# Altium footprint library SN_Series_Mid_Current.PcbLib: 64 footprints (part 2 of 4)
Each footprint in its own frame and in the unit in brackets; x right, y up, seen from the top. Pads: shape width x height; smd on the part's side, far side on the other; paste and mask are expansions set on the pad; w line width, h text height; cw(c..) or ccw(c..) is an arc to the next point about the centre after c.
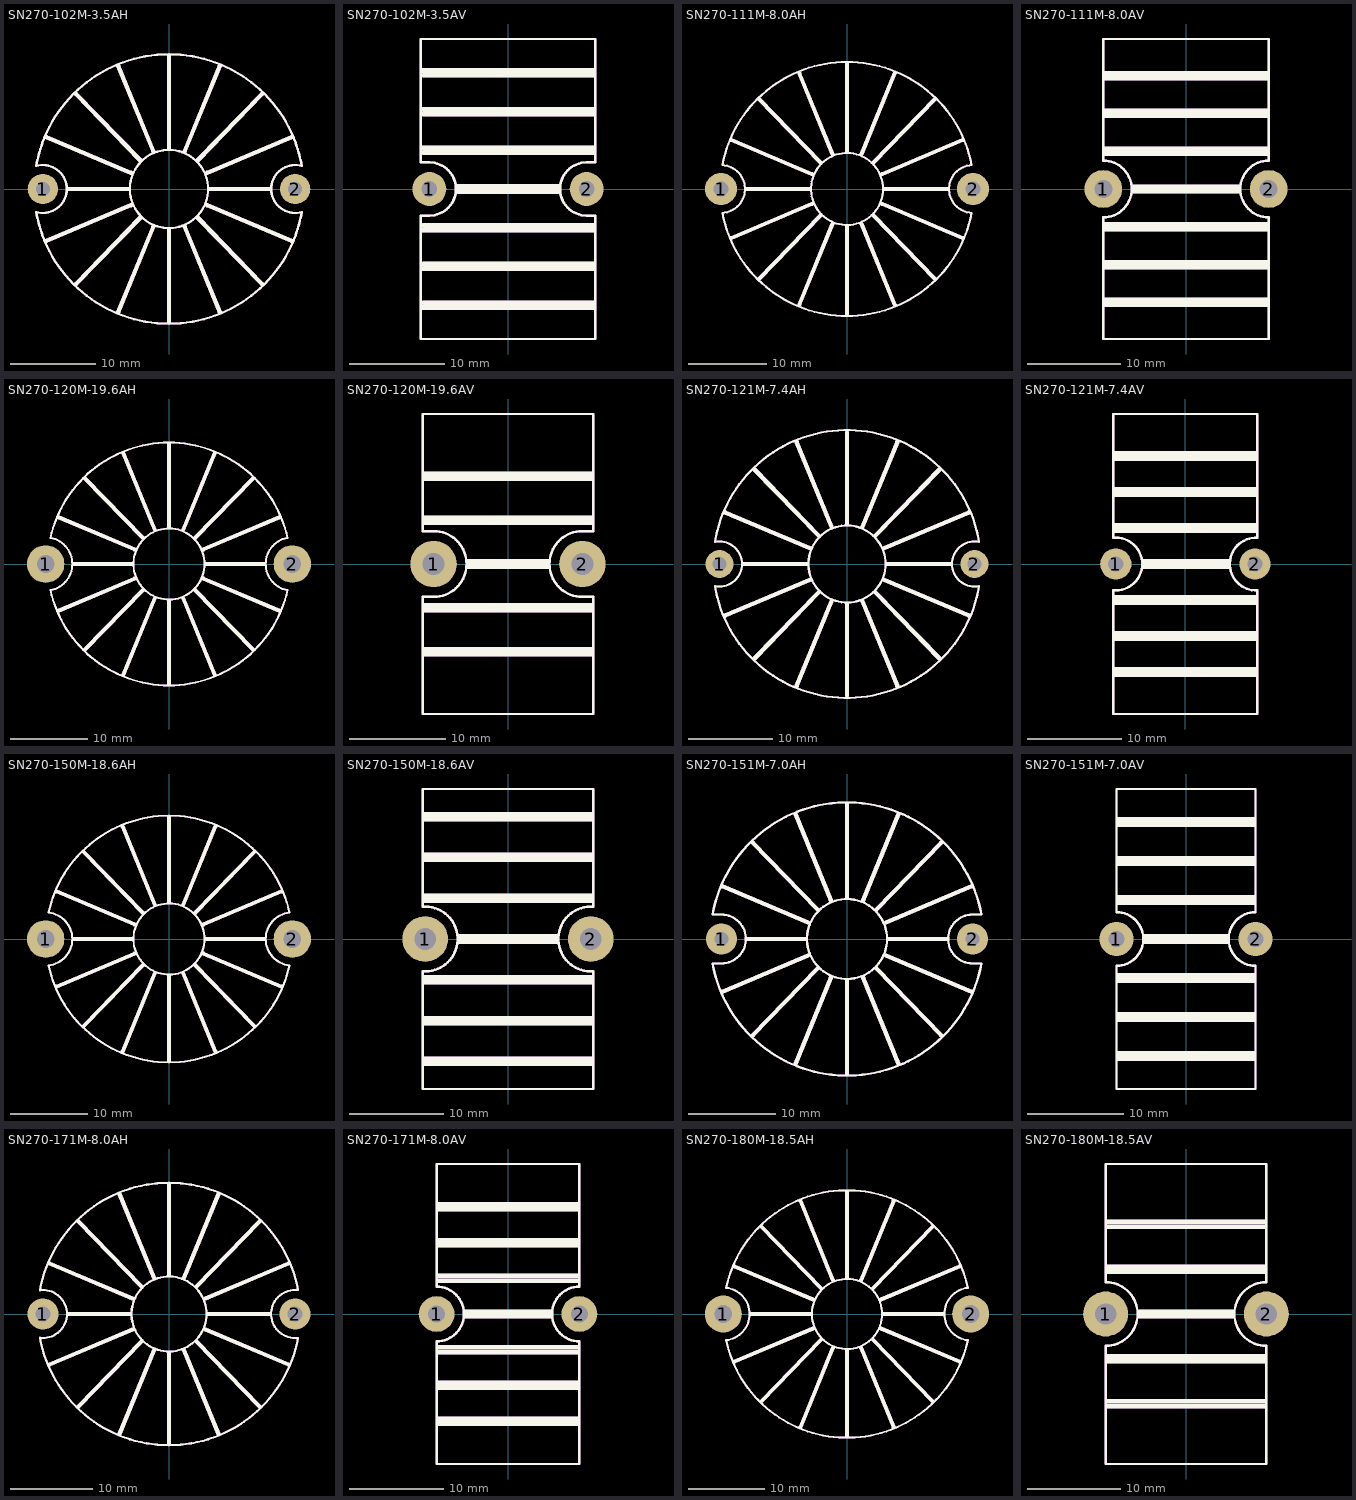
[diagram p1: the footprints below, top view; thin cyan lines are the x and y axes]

## SN270-102M-3.5AH [mil]
pads (2):
  round 140 hole 65: 1(-580,0) 2(580,0)
Top Overlay:
  circle w10: c0,0 r180
  lines w10: -610.95,-105.56 ccw(c0,0) 610.95,-105.56 cw(c580,0) 610.95,105.56 ccw(c0,0) -610.95,105.56 cw(c-580,0) -610.95,-105.56
  lines w19.68: -566.62,-240.1 -175.3,-74.28 ; -566.62,240.1 -175.3,74.28 ; -465,0 -185,0 ; -428.33,-437.64 -132.5,-132.5 ; -428.33,437.64 -132.5,132.5 ; -233.63,-567.25 -72.46,-173.99 ; -233.63,567.25 -72.46,173.99 ; 0,-610 0,-185 ; 0,185 0,610 ; 72.46,-173.99 233.63,-567.25 ; 72.46,173.99 233.63,567.25 ; 132.5,-132.5 428.33,-437.64 ; 132.5,132.5 428.33,437.64 ; 175.3,-74.28 566.62,-240.1 ; 175.3,74.28 566.62,240.1 ; 185,0 465,0
Mechanical 29:
  circle w10: c0,0 r180
  lines w10: -610.95,-105.56 ccw(c0,0) 610.95,-105.56 cw(c580,0) 610.95,105.56 ccw(c0,0) -610.95,105.56 cw(c-580,0) -610.95,-105.56
  lines w19.68: -566.62,-240.1 -175.3,-74.28 ; -566.62,240.1 -175.3,74.28 ; -465,0 -185,0 ; -428.33,-437.64 -132.5,-132.5 ; -428.33,437.64 -132.5,132.5 ; -233.63,-567.25 -72.46,-173.99 ; -233.63,567.25 -72.46,173.99 ; 0,-610 0,-185 ; 0,185 0,610 ; 72.46,-173.99 233.63,-567.25 ; 72.46,173.99 233.63,567.25 ; 132.5,-132.5 428.33,-437.64 ; 132.5,132.5 428.33,437.64 ; 175.3,-74.28 566.62,-240.1 ; 175.3,74.28 566.62,240.1 ; 185,0 465,0
  text "'.Designator'" at -290,145.15 h400

## SN270-102M-3.5AV [mil]
pads (2):
  round 140 hole 65: 1(-325,0) 2(325,0)
Top Overlay:
  lines w10: -360,-620 360,-620 360,-110 325,-110 cw(c325,0) 325,110 360,110 360,620 -360,620 -360,110 -325,110 cw(c-325,0) -325,-110 -360,-110 -360,-620
  lines w19.68: -355,-490 355,-490 ; -355,-330 355,-330 ; -355,-170 355,-170 ; -355,170 355,170 ; -355,330 355,330 ; -355,490 355,490 ; -350,-470 355,-470 ; -350,-310 355,-310 ; -350,-150 355,-150 ; -350,150 355,150 ; -350,310 355,310 ; -350,470 355,470 ; -210,-10 208,-10 ; -210,10 208,10
Mechanical 29:
  lines w10: -360,-620 360,-620 360,-110 325,-110 cw(c325,0) 325,110 360,110 360,620 -360,620 -360,110 -325,110 cw(c-325,0) -325,-110 -360,-110 -360,-620
  lines w19.68: -355,-490 355,-490 ; -355,-330 355,-330 ; -355,-170 355,-170 ; -355,170 355,170 ; -355,330 355,330 ; -355,490 355,490 ; -350,-470 355,-470 ; -350,-310 355,-310 ; -350,-150 355,-150 ; -350,150 355,150 ; -350,310 355,310 ; -350,470 355,470 ; -210,-10 208,-10 ; -210,10 208,10
  text "'.Designator'" at -1750,-64.85 h400

## SN270-111M-8.0AH [mil]
pads (2):
  round 160 hole 76: 1(-630,0) 2(630,0)
Top Overlay:
  circle w10: c0,0 r180
  lines w10: -623.53,-120.17 ccw(c0,0) 623.53,-120.17 ; -623.54,-119.83 ccw(c-630,0) -623.54,119.83 ; -623.53,120.17 cw(c0,0) 623.53,120.17 ; 623.54,-119.83 cw(c630,0) 623.54,119.83
  lines w19.68: -579.73,-245.65 -175.3,-74.28 ; -579.73,245.65 -175.3,74.28 ; -505,0 -185,0 ; -440.16,-449.85 -132.5,-132.5 ; -440.16,449.85 -132.5,132.5 ; -238.3,-578.65 -72.46,-173.99 ; -238.3,578.65 -72.46,173.99 ; 0,-630 0,-185 ; 0,185 0,630 ; 72.46,-173.99 239.02,-580.4 ; 72.46,173.99 239.02,580.4 ; 132.5,-132.5 440.16,-449.85 ; 132.5,132.5 440.16,449.85 ; 175.3,-74.28 579.73,-245.65 ; 175.3,74.28 579.73,245.65 ; 185,0 505,0
Mechanical 29:
  circle w10: c0,0 r180
  lines w10: -623.53,-120.17 ccw(c0,0) 623.53,-120.17 ; -623.54,-119.83 ccw(c-630,0) -623.54,119.83 ; -623.53,120.17 cw(c0,0) 623.53,120.17 ; 623.54,-119.83 cw(c630,0) 623.54,119.83
  lines w19.68: -579.73,-245.65 -175.3,-74.28 ; -579.73,245.65 -175.3,74.28 ; -505,0 -185,0 ; -440.16,-449.85 -132.5,-132.5 ; -440.16,449.85 -132.5,132.5 ; -238.3,-578.65 -72.46,-173.99 ; -238.3,578.65 -72.46,173.99 ; 0,-630 0,-185 ; 0,185 0,630 ; 72.46,-173.99 239.02,-580.4 ; 72.46,173.99 239.02,580.4 ; 132.5,-132.5 440.16,-449.85 ; 132.5,132.5 440.16,449.85 ; 175.3,-74.28 579.73,-245.65 ; 175.3,74.28 579.73,245.65 ; 185,0 505,0
  text "'.Designator'" at -290,145.15 h400

## SN270-111M-8.0AV [mil]
pads (2):
  round 160 hole 76: 1(-350,0) 2(350,0)
Top Overlay:
  lines w10: -350,-635 350,-635 350,-120 cw(c350,0) 350,120 350,635 -350,635 -350,120 cw(c-350,0) -350,-120 -350,-635
  lines w19.68: -345,-490 345,-490 ; -345,-470 345,-470 ; -345,-330 345,-330 ; -345,-310 345,-310 ; -345,-170 345,-170 ; -345,-150 345,-150 ; -345,150 345,150 ; -345,170 345,170 ; -345,310 345,310 ; -345,330 345,330 ; -345,470 345,470 ; -345,490 345,490 ; -225,-10 225,-10 ; -225,10 225,10
Mechanical 29:
  lines w10: -350,-635 350,-635 350,-120 cw(c350,0) 350,120 350,635 -350,635 -350,120 cw(c-350,0) -350,-120 -350,-635
  lines w19.68: -345,-490 345,-490 ; -345,-470 345,-470 ; -345,-330 345,-330 ; -345,-310 345,-310 ; -345,-170 345,-170 ; -345,-150 345,-150 ; -345,150 345,150 ; -345,170 345,170 ; -345,310 345,310 ; -345,330 345,330 ; -345,470 345,470 ; -345,490 345,490 ; -225,-10 225,-10 ; -225,10 225,10
  text "'.Designator'" at -1750,-64.85 h400

## SN270-120M-19.6AH [mil]
pads (2):
  round 190 hole 90: 1(-625,0) 2(625,0)
Top Overlay:
  circle w10: c0,0 r180
  lines w10: -600.5,-132.76 ccw(c0,0) 600.5,-132.76 cw(c625,0) 600.5,132.76 ccw(c0,0) -600.5,132.76 cw(c-625,0) -600.5,-132.76
  lines w19.68: -562.02,-238.14 -175.3,-74.28 ; -562.02,238.14 -175.3,74.28 ; -485,0 -185,0 ; -424.85,-434.05 -132.5,-132.5 ; -424.85,434.05 -132.5,132.5 ; -231.73,-562.62 -72.46,-173.99 ; -231.73,562.62 -72.46,173.99 ; 0,-610 0,-185 ; 0,185 0,610 ; 72.46,-173.99 231.73,-562.62 ; 72.46,173.99 231.73,562.62 ; 132.5,-132.5 424.85,-434.05 ; 132.5,132.5 424.85,434.05 ; 175.3,-74.28 562.02,-238.14 ; 175.3,74.28 562.02,238.14 ; 185,0 485,0
Mechanical 29:
  circle w10: c0,0 r180
  lines w10: -600.5,-132.76 ccw(c0,0) 600.5,-132.76 cw(c625,0) 600.5,132.76 ccw(c0,0) -600.5,132.76 cw(c-625,0) -600.5,-132.76
  lines w19.68: -562.02,-238.14 -175.3,-74.28 ; -562.02,238.14 -175.3,74.28 ; -485,0 -185,0 ; -424.85,-434.05 -132.5,-132.5 ; -424.85,434.05 -132.5,132.5 ; -231.73,-562.62 -72.46,-173.99 ; -231.73,562.62 -72.46,173.99 ; 0,-610 0,-185 ; 0,185 0,610 ; 72.46,-173.99 231.73,-562.62 ; 72.46,173.99 231.73,562.62 ; 132.5,-132.5 424.85,-434.05 ; 132.5,132.5 424.85,434.05 ; 175.3,-74.28 562.02,-238.14 ; 175.3,74.28 562.02,238.14 ; 185,0 485,0
  text "'.Designator'" at -290,145.15 h400

## SN270-120M-19.6AV [mil]
pads (2):
  round 190 hole 90: 1(-305,0) 2(305,0)
Top Overlay:
  lines w10: -350,-615 -350,-135 -305,-135 ccw(c-305,0) -305,135 -350,135 -350,615 350,615 350,135 305,135 ccw(c305,0) 305,-135 350,-135 350,-615 -350,-615
  lines w19.68: -345,-370 345,-370 ; -345,-350 345,-350 ; -345,-190 345,-190 ; -345,-170 345,-170 ; -345,170 345,170 ; -345,190 345,190 ; -345,350 345,350 ; -345,370 345,370 ; -165,-10 165,-10 ; -165,10 165,10
Mechanical 29:
  lines w10: -350,-615 -350,-135 -305,-135 ccw(c-305,0) -305,135 -350,135 -350,615 350,615 350,135 305,135 ccw(c305,0) 305,-135 350,-135 350,-615 -350,-615
  lines w19.68: -345,-370 345,-370 ; -345,-350 345,-350 ; -345,-190 345,-190 ; -345,-170 345,-170 ; -345,170 345,170 ; -345,190 345,190 ; -345,350 345,350 ; -345,370 345,370 ; -165,-10 165,-10 ; -165,10 165,10
  text "'.Designator'" at -1750,-64.85 h400

## SN270-121M-7.4AH [mil]
pads (2):
  round 130 hole 64: 1(-595,0) 2(595,0)
Top Overlay:
  circle w10: c0,0 r180
  lines w10: -616.46,-102.94 ccw(c0,0) 616.46,-102.94 ; -616.46,102.94 cw(c0,0) 616.46,102.94 ; -616.05,-102.87 ccw(c-595,0) -616.05,102.87 ; 616.05,-102.87 cw(c595,0) 616.05,102.87
  lines w19.68: -569.45,-241.29 -175.3,-74.28 ; -569.45,241.29 -175.3,74.28 ; -485,0 -185,0 ; -430.31,-439.69 -132.5,-132.5 ; -430.31,439.69 -132.5,132.5 ; -234.79,-570.09 -72.46,-173.99 ; -234.79,570.09 -72.46,173.99 ; 0,-615 0,-185 ; 0,185 0,615 ; 72.46,-173.99 234.79,-570.09 ; 72.46,173.99 234.79,570.09 ; 132.5,-132.5 430.31,-439.69 ; 132.5,132.5 430.31,439.69 ; 175.3,-74.28 569.45,-241.29 ; 175.3,74.28 569.45,241.29 ; 185,0 485,0
Mechanical 29:
  circle w10: c0,0 r180
  lines w10: -616.46,-102.94 ccw(c0,0) 616.46,-102.94 ; -616.46,102.94 cw(c0,0) 616.46,102.94 ; -616.05,-102.87 ccw(c-595,0) -616.05,102.87 ; 616.05,-102.87 cw(c595,0) 616.05,102.87
  lines w19.68: -569.45,-241.29 -175.3,-74.28 ; -569.45,241.29 -175.3,74.28 ; -485,0 -185,0 ; -430.31,-439.69 -132.5,-132.5 ; -430.31,439.69 -132.5,132.5 ; -234.79,-570.09 -72.46,-173.99 ; -234.79,570.09 -72.46,173.99 ; 0,-615 0,-185 ; 0,185 0,615 ; 72.46,-173.99 234.79,-570.09 ; 72.46,173.99 234.79,570.09 ; 132.5,-132.5 430.31,-439.69 ; 132.5,132.5 430.31,439.69 ; 175.3,-74.28 569.45,-241.29 ; 175.3,74.28 569.45,241.29 ; 185,0 485,0
  text "'.Designator'" at -290,145.15 h400

## SN270-121M-7.4AV [mil]
pads (2):
  round 130 hole 64: 1(-290,0) 2(290,0)
Top Overlay:
  lines w10: -300,-109.59 -300,-625 300,-625 300,-109.86 ; -300,109.59 -300,625 300,625 300,109.9 ; -299.54,-109.59 ccw(c-290,0) -299.54,109.59 ; 299.7,109.9 ccw(c295,0) 300,-109.89
  lines w19.68: -295,-460 295,-460 ; -295,-440 295,-440 ; -295,-310 295,-310 ; -295,-290 295,-290 ; -295,-160 295,-160 ; -295,-140 295,-140 ; -295,140 295,140 ; -295,160 295,160 ; -295,290 295,290 ; -295,310 295,310 ; -295,440 295,440 ; -295,460 295,460 ; -174,-10 178,-10 ; -174,10 178,10
Mechanical 29:
  lines w10: -300,-109.59 -300,-625 300,-625 300,-109.86 ; -300,109.59 -300,625 300,625 300,109.9 ; -299.54,-109.59 ccw(c-290,0) -299.54,109.59 ; 299.7,109.9 ccw(c295,0) 300,-109.89
  lines w19.68: -295,-460 295,-460 ; -295,-440 295,-440 ; -295,-310 295,-310 ; -295,-290 295,-290 ; -295,-160 295,-160 ; -295,-140 295,-140 ; -295,140 295,140 ; -295,160 295,160 ; -295,290 295,290 ; -295,310 295,310 ; -295,440 295,440 ; -295,460 295,460 ; -174,-10 178,-10 ; -174,10 178,10
  text "'.Designator'" at -1750,-64.85 h400

## SN270-150M-18.6AH [mil]
pads (2):
  round 190 hole 90: 1(-625,0) 2(625,0)
Top Overlay:
  circle w10: c0,0 r180
  lines w10: -610.43,134.21 cw(c-625,0) -610.42,-134.21 ccw(c0,0) 610.42,-134.21 cw(c625,0) 610.43,134.21 ; -610.42,134.21 cw(c0,0) 610.44,134.11
  lines w19.68: -569.45,-241.29 -175.3,-74.28 ; -569.45,241.29 -175.3,74.28 ; -485,0 -185,0 ; -430.31,-439.69 -132.5,-132.5 ; -430.31,439.69 -132.5,132.5 ; -234.79,-570.09 -72.46,-173.99 ; -234.79,570.09 -72.46,173.99 ; 0,-615 0,-185 ; 0,185 0,615 ; 72.46,-173.99 234.79,-570.09 ; 72.46,173.99 234.79,570.09 ; 132.5,-132.5 430.31,-439.69 ; 132.5,132.5 430.31,439.69 ; 175.3,-74.28 569.45,-241.29 ; 175.3,74.28 569.45,241.29 ; 185,0 485,0
Mechanical 29:
  circle w10: c0,0 r180
  lines w10: -610.43,134.21 cw(c-625,0) -610.42,-134.21 ccw(c0,0) 610.42,-134.21 cw(c625,0) 610.43,134.21 ; -610.42,134.21 cw(c0,0) 610.44,134.11
  lines w19.68: -569.45,-241.29 -175.3,-74.28 ; -569.45,241.29 -175.3,74.28 ; -485,0 -185,0 ; -430.31,-439.69 -132.5,-132.5 ; -430.31,439.69 -132.5,132.5 ; -234.79,-570.09 -72.46,-173.99 ; -234.79,570.09 -72.46,173.99 ; 0,-615 0,-185 ; 0,185 0,615 ; 72.46,-173.99 234.79,-570.09 ; 72.46,173.99 234.79,570.09 ; 132.5,-132.5 430.31,-439.69 ; 132.5,132.5 430.31,439.69 ; 175.3,-74.28 569.45,-241.29 ; 175.3,74.28 569.45,241.29 ; 185,0 485,0
  text "'.Designator'" at -290,145.15 h400

## SN270-150M-18.6AV [mil]
pads (2):
  round 190 hole 90: 1(-345,0) 2(345,0)
Top Overlay:
  lines w10: -355,-135 -355,-625 355,-625 355,-135 ; -355,135 -355,625 355,625 355,135 ; -354.97,-134.63 ccw(c-345,0) -354.97,134.63 ; 354.97,-134.63 cw(c345,0) 354.97,134.63
  lines w19.68: -350,-520 350,-520 ; -350,-500 350,-500 ; -350,-350 350,-350 ; -350,-330 350,-330 ; -350,-180 350,-180 ; -350,-160 350,-160 ; -350,160 350,160 ; -350,180 350,180 ; -350,330 350,330 ; -350,350 350,350 ; -350,500 350,500 ; -350,520 350,520 ; -205,-10 205,-10 ; -205,10 205,10
Mechanical 29:
  lines w10: -355,-135 -355,-625 355,-625 355,-135 ; -355,135 -355,625 355,625 355,135 ; -354.97,-134.63 ccw(c-345,0) -354.97,134.63 ; 354.97,-134.63 cw(c345,0) 354.97,134.63
  lines w19.68: -350,-520 350,-520 ; -350,-500 350,-500 ; -350,-350 350,-350 ; -350,-330 350,-330 ; -350,-180 350,-180 ; -350,-160 350,-160 ; -350,160 350,160 ; -350,180 350,180 ; -350,330 350,330 ; -350,350 350,350 ; -350,500 350,500 ; -350,520 350,520 ; -205,-10 205,-10 ; -205,10 205,10
  text "'.Designator'" at -1750,-64.85 h400

## SN270-151M-7.0AH [mil]
pads (2):
  round 140 hole 64: 1(-565,0) 2(565,0)
Top Overlay:
  circle w10: c0,0 r180
  lines w10: -604.94,-110.77 ccw(c0,0) 605.08,-110.02 565,-110 cw(c565,0) 565,110 605.08,110 ccw(c0,0) -604.94,110.77 ; -604.94,-110 -565,-110 ccw(c-565,0) -565,110 -604.94,110
  lines w19.68: -562.02,-238.14 -175.3,-74.28 ; -562.02,238.14 -175.3,74.28 ; -450,0 -185,0 ; -424.85,-434.05 -132.5,-132.5 ; -424.85,434.05 -132.5,132.5 ; -231.73,-562.62 -72.46,-173.99 ; -231.73,562.62 -72.46,173.99 ; 0,-610 0,-185 ; 0,185 0,610 ; 72.46,-173.99 231.73,-562.62 ; 72.46,173.99 231.73,562.62 ; 132.5,-132.5 424.85,-434.05 ; 132.5,132.5 424.85,434.05 ; 175.3,-74.28 562.02,-238.14 ; 175.3,74.28 562.02,238.14 ; 185,0 450,0
Mechanical 29:
  circle w10: c0,0 r180
  lines w10: -604.94,-110.77 ccw(c0,0) 605.08,-110.02 565,-110 cw(c565,0) 565,110 605.08,110 ccw(c0,0) -604.94,110.77 ; -604.94,-110 -565,-110 ccw(c-565,0) -565,110 -604.94,110
  lines w19.68: -562.02,-238.14 -175.3,-74.28 ; -562.02,238.14 -175.3,74.28 ; -450,0 -185,0 ; -424.85,-434.05 -132.5,-132.5 ; -424.85,434.05 -132.5,132.5 ; -231.73,-562.62 -72.46,-173.99 ; -231.73,562.62 -72.46,173.99 ; 0,-610 0,-185 ; 0,185 0,610 ; 72.46,-173.99 231.73,-562.62 ; 72.46,173.99 231.73,562.62 ; 132.5,-132.5 424.85,-434.05 ; 132.5,132.5 424.85,434.05 ; 175.3,-74.28 562.02,-238.14 ; 175.3,74.28 562.02,238.14 ; 185,0 450,0
  text "'.Designator'" at -290,145.15 h400

## SN270-151M-7.0AV [mil]
pads (2):
  round 140 hole 64: 1(-285,0) 2(285,0)
Top Overlay:
  lines w10: 285,-114.48 285,-615 -285,-615 -285,-110 ccw(c-285,0) -285,110 -285,615 285,615 285,110 ccw(c285,0) 285,-110
  lines w19.68: -280,-490 280,-490 ; -280,-470 280,-470 ; -280,-330 280,-330 ; -280,-310 280,-310 ; -280,-170 280,-170 ; -280,-150 280,-150 ; -280,150 280,150 ; -280,170 280,170 ; -280,310 280,310 ; -280,330 280,330 ; -280,470 280,470 ; -280,490 280,490 ; -170,-10 170,-10 ; -170,10 170,10
Mechanical 29:
  lines w10: 285,-114.48 285,-615 -285,-615 -285,-110 ccw(c-285,0) -285,110 -285,615 285,615 285,110 ccw(c285,0) 285,-110
  lines w19.68: -280,-490 280,-490 ; -280,-470 280,-470 ; -280,-330 280,-330 ; -280,-310 280,-310 ; -280,-170 280,-170 ; -280,-150 280,-150 ; -280,150 280,150 ; -280,170 280,170 ; -280,310 280,310 ; -280,330 280,330 ; -280,470 280,470 ; -280,490 280,490 ; -170,-10 170,-10 ; -170,10 170,10
  text "'.Designator'" at -1750,-64.85 h400

## SN270-171M-8.0AH [mil]
pads (2):
  round 150 hole 70: 1(-605,0) 2(605,0)
Top Overlay:
  circle w10: c0,0 r180
  lines w10: -619.5,-114.53 ccw(c0,0) 619.5,-114.53 ; -619.5,114.53 cw(c0,0) 619.5,114.53 ; -619.45,-114.09 ccw(c-605,0) -619.45,114.09 ; 618.05,-114.26 cw(c605,0) 618.05,114.26
  lines w19.68: -575.83,-244 -175.3,-74.28 ; -575.83,244 -175.3,74.28 ; -485,0 -185,0 ; -435.29,-444.82 -132.5,-132.5 ; -435.29,444.82 -132.5,132.5 ; -237.42,-576.5 -72.46,-173.99 ; -237.42,576.5 -72.46,173.99 ; 0,-620 0,-185 ; 0,185 0,620 ; 72.46,-173.99 237.42,-576.5 ; 72.46,173.99 237.42,576.5 ; 132.5,-132.5 435.29,-444.82 ; 132.5,132.5 435.29,444.82 ; 175.3,-74.28 575.83,-244 ; 175.3,74.28 575.83,244 ; 185,0 485,0
Mechanical 29:
  circle w10: c0,0 r180
  lines w10: -619.5,-114.53 ccw(c0,0) 619.5,-114.53 ; -619.5,114.53 cw(c0,0) 619.5,114.53 ; -619.45,-114.09 ccw(c-605,0) -619.45,114.09 ; 618.05,-114.26 cw(c605,0) 618.05,114.26
  lines w19.68: -575.83,-244 -175.3,-74.28 ; -575.83,244 -175.3,74.28 ; -485,0 -185,0 ; -435.29,-444.82 -132.5,-132.5 ; -435.29,444.82 -132.5,132.5 ; -237.42,-576.5 -72.46,-173.99 ; -237.42,576.5 -72.46,173.99 ; 0,-620 0,-185 ; 0,185 0,620 ; 72.46,-173.99 237.42,-576.5 ; 72.46,173.99 237.42,576.5 ; 132.5,-132.5 435.29,-444.82 ; 132.5,132.5 435.29,444.82 ; 175.3,-74.28 575.83,-244 ; 175.3,74.28 575.83,244 ; 185,0 485,0
  text "'.Designator'" at -290,145.15 h400

## SN270-171M-8.0AV [mil]
pads (2):
  round 150 hole 70: 1(-300,0) 2(300,0)
Top Overlay:
  lines w10: -300,-630 -300,-115 ccw(c-300,0) -300,115 -300,630 300,630 300,115 ccw(c300,0) 300,-115 300,-630 -300,-630
  lines w19.68: -295,-460 295,-460 ; -295,-440 295,-440 ; -295,-310 295,-310 ; -295,-290 295,-290 ; -295,-160 295,-160 ; -295,-140 295,-140 ; -295,140 295,140 ; -295,160 295,160 ; -295,290 295,290 ; -295,310 295,310 ; -295,440 295,440 ; -295,460 295,460 ; -180,-10 180,-10 ; -180,10 180,10
Mechanical 29:
  lines w10: -300,-630 -300,-115 ccw(c-300,0) -300,115 -300,630 300,630 300,115 ccw(c300,0) 300,-115 300,-630 -300,-630
  lines w19.68: -295,-460 295,-460 ; -295,-440 295,-440 ; -295,-310 295,-310 ; -295,-290 295,-290 ; -295,-160 295,-160 ; -295,-140 295,-140 ; -295,140 295,140 ; -295,160 295,160 ; -295,290 295,290 ; -295,310 295,310 ; -295,440 295,440 ; -295,460 295,460 ; -180,-10 180,-10 ; -180,10 180,10
  text "'.Designator'" at -1750,-64.85 h400

## SN270-180M-18.5AH [mil]
pads (2):
  round 190 hole 90: 1(-635,0) 2(635,0)
Top Overlay:
  circle w10: c0,0 r180
  lines w10: -621.18,-134.29 ccw(c-635,0) -621.18,134.29 ; -620.66,-134.18 ccw(c0,0) 620.65,-134.24 ; -620.65,134.24 cw(c0,0) 620.66,134.18 ; 621.18,-134.29 cw(c635,0) 621.18,134.29
  lines w19.68: -579.73,-245.65 -175.3,-74.28 ; -579.73,245.65 -175.3,74.28 ; -495,0 -185,0 ; -440.16,-449.85 -132.5,-132.5 ; -440.16,449.85 -132.5,132.5 ; -238.3,-578.65 -72.46,-173.99 ; -238.3,578.65 -72.46,173.99 ; 0,-630 0,-185 ; 0,185 0,630 ; 72.46,-173.99 239.02,-580.4 ; 72.46,173.99 239.02,580.4 ; 132.5,-132.5 440.16,-449.85 ; 132.5,132.5 440.16,449.85 ; 175.3,-74.28 579.73,-245.65 ; 175.3,74.28 579.73,245.65 ; 185,0 495,0
Mechanical 29:
  circle w10: c0,0 r180
  lines w10: -621.18,-134.29 ccw(c-635,0) -621.18,134.29 ; -620.66,-134.18 ccw(c0,0) 620.65,-134.24 ; -620.65,134.24 cw(c0,0) 620.66,134.18 ; 621.18,-134.29 cw(c635,0) 621.18,134.29
  lines w19.68: -579.73,-245.65 -175.3,-74.28 ; -579.73,245.65 -175.3,74.28 ; -495,0 -185,0 ; -440.16,-449.85 -132.5,-132.5 ; -440.16,449.85 -132.5,132.5 ; -238.3,-578.65 -72.46,-173.99 ; -238.3,578.65 -72.46,173.99 ; 0,-630 0,-185 ; 0,185 0,630 ; 72.46,-173.99 239.02,-580.4 ; 72.46,173.99 239.02,580.4 ; 132.5,-132.5 440.16,-449.85 ; 132.5,132.5 440.16,449.85 ; 175.3,-74.28 579.73,-245.65 ; 175.3,74.28 579.73,245.65 ; 185,0 495,0
  text "'.Designator'" at -290,145.15 h400

## SN270-180M-18.5AV [mil]
pads (2):
  round 190 hole 90: 1(-340,0) 2(340,0)
Top Overlay:
  lines w10: -340,-635 -340,-135 ccw(c-340,0) -340,135 -340,635 340,635 340,135 ccw(c340,0) 340,-135 340,-635 -340,-635
  lines w19.68: -335,-390 335,-390 ; -335,-370 335,-370 ; -335,-200 335,-200 ; -335,-180 335,-180 ; -335,180 335,180 ; -335,200 335,200 ; -335,370 335,370 ; -335,390 335,390 ; -200,-10 200,-10 ; -200,10 200,10
Mechanical 29:
  lines w10: -340,-635 -340,-135 ccw(c-340,0) -340,135 -340,635 340,635 340,135 ccw(c340,0) 340,-135 340,-635 -340,-635
  lines w19.68: -335,-390 335,-390 ; -335,-370 335,-370 ; -335,-200 335,-200 ; -335,-180 335,-180 ; -335,180 335,180 ; -335,200 335,200 ; -335,370 335,370 ; -335,390 335,390 ; -200,-10 200,-10 ; -200,10 200,10
  text "'.Designator'" at -1750,-64.85 h400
